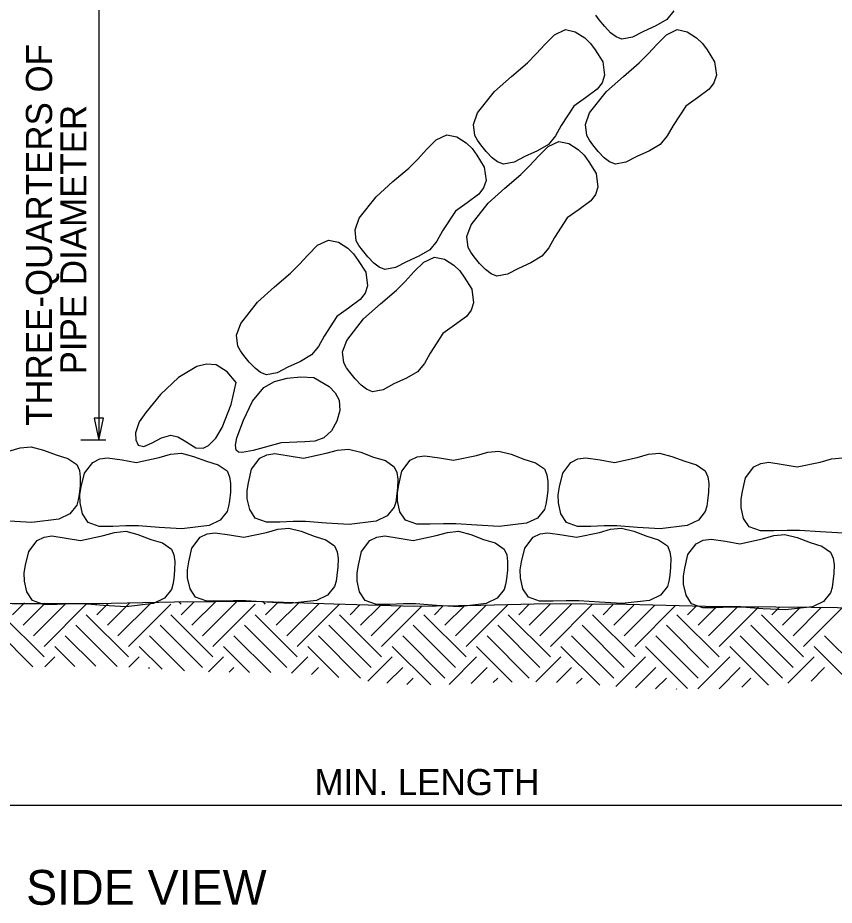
# Model space of a CAD drawing. Extents: x -439.1 to -407.9, y -458.1 to -436.2.
# Drawn here: x -428.69 to -424, y -444.35 to -439.25 of the extents above; entities that cross this region are included whole.
import ezdxf

# ---------------------------------------------------------------- set-up
doc = ezdxf.new("R2010")
doc.units = 0
doc.layers.add('Level 4', color=7, linetype='Continuous')

msp = doc.modelspace()

# ---------------------------------------------------------------- linework, layer by layer
at = {"layer": 'Level 4'}
for p, q in [((-428.2285, -439.0536), (-428.2285, -441.6773)), ((-428.1891, -441.6773), (-428.3314, -441.6773)), ((-427.6944, -442.741), (-427.5572, -442.6037)), ((-427.6338, -442.8016), (-427.4355, -442.6033)), ((-427.2701, -442.6197), (-427.2849, -442.6049)), ((-428.7249, -442.6804), (-428.6565, -442.612)), ((-428.6643, -442.741), (-428.5371, -442.6138)), ((-428.6037, -442.8016), (-428.4176, -442.6156)), ((-428.543, -442.8622), (-428.3006, -442.6197)), ((-428.24, -442.6197), (-428.2417, -442.618)), ((-428.24, -442.6804), (-428.1764, -442.6168)), ((-428.1794, -442.741), (-428.0525, -442.6141)), ((-428.1187, -442.8016), (-427.9282, -442.6111)), ((-428.0581, -442.8622), (-427.8157, -442.6197)), ((-427.7551, -442.6197), (-427.7676, -442.6072)), ((-427.7551, -442.6804), (-427.6801, -442.6054)), ((-427.5732, -442.8622), (-427.3308, -442.6197)), ((-427.2701, -442.6804), (-427.1967, -442.6069)), ((-427.2095, -442.741), (-427.0795, -442.611)), ((-427.1489, -442.8016), (-426.9629, -442.6155)), ((-427.0883, -442.8622), (-426.8464, -442.6203)), ((-426.7852, -442.6804), (-426.7299, -442.625)), ((-426.7246, -442.741), (-426.6124, -442.6288)), ((-426.664, -442.8016), (-426.4938, -442.6313)), ((-426.6034, -442.8622), (-426.3736, -442.6324)), ((-426.3003, -442.6804), (-426.2515, -442.6316)), ((-426.2397, -442.741), (-426.1279, -442.6292)), ((-426.1791, -442.8016), (-426.0036, -442.6261)), ((-426.1185, -442.8622), (-425.879, -442.6227)), ((-425.8154, -442.6804), (-425.7549, -442.6198)), ((-425.7548, -442.741), (-425.6323, -442.6184)), ((-425.6942, -442.8016), (-425.5129, -442.6203)), ((-425.6336, -442.8622), (-425.3936, -442.6222)), ((-425.3305, -442.6804), (-425.2743, -442.6241)), ((-425.2699, -442.741), (-425.1549, -442.626)), ((-425.2093, -442.8016), (-425.0356, -442.6279)), ((-425.1487, -442.8622), (-424.9163, -442.6298)), ((-424.8456, -442.6804), (-424.7969, -442.6317)), ((-424.785, -442.741), (-424.6776, -442.6336)), ((-424.7244, -442.8016), (-424.5582, -442.6354)), ((-424.6637, -442.8622), (-424.4383, -442.6367)), ((-424.3607, -442.6804), (-424.3181, -442.6378)), ((-424.3001, -442.741), (-424.1978, -442.6387)), ((-424.2394, -442.8016), (-424.0775, -442.6396)), ((-424.1788, -442.8622), (-423.9573, -442.6407)), ((-428.543, -442.9228), (-428.7855, -442.6804)), ((-428.0581, -442.9228), (-428.3006, -442.6804)), ((-427.5732, -442.9228), (-427.8157, -442.6804)), ((-427.0883, -442.9228), (-427.3308, -442.6804)), ((-426.6034, -442.9228), (-426.8458, -442.6804)), ((-426.1185, -442.9228), (-426.3609, -442.6804)), ((-425.6336, -442.9228), (-425.876, -442.6804)), ((-425.1487, -442.9228), (-425.3911, -442.6804)), ((-424.6637, -442.9228), (-424.9062, -442.6804)), ((-424.1788, -442.9228), (-424.4213, -442.6804)), ((-428.6075, -442.9796), (-428.8461, -442.741)), ((-428.1234, -442.9787), (-428.3612, -442.741)), ((-427.6338, -442.9834), (-427.8763, -442.741)), ((-427.1489, -442.9834), (-427.3914, -442.741)), ((-426.664, -442.9834), (-426.9065, -442.741)), ((-426.1791, -442.9834), (-426.4215, -442.741)), ((-425.6942, -442.9834), (-425.9366, -442.741)), ((-425.2093, -442.9834), (-425.4517, -442.741)), ((-424.7244, -442.9834), (-424.9668, -442.741)), ((-424.2394, -442.9834), (-424.4819, -442.741)), ((-428.2468, -442.9766), (-428.4218, -442.8016)), ((-427.7356, -443.0029), (-427.9369, -442.8016)), ((-427.2407, -443.0128), (-427.452, -442.8016)), ((-426.7246, -443.044), (-426.9671, -442.8016)), ((-426.2397, -443.044), (-426.4822, -442.8016)), ((-425.7548, -443.044), (-425.9972, -442.8016)), ((-425.2699, -443.044), (-425.5123, -442.8016)), ((-424.785, -443.044), (-425.0274, -442.8016)), ((-424.3001, -443.044), (-424.5425, -442.8016)), ((-423.8278, -443.0314), (-424.0576, -442.8016)), ((-428.3675, -442.9772), (-428.4824, -442.8622)), ((-427.8656, -442.9941), (-427.9975, -442.8622)), ((-427.3632, -443.0117), (-427.5126, -442.8622)), ((-426.8488, -443.0411), (-427.0277, -442.8622)), ((-426.3216, -443.0834), (-426.5428, -442.8622)), ((-425.853, -443.0671), (-426.0579, -442.8622)), ((-425.3493, -443.0858), (-425.5729, -442.8622)), ((-424.8456, -443.1047), (-425.088, -442.8622)), ((-424.381, -443.0843), (-424.6031, -442.8622)), ((-423.9382, -443.0422), (-424.1182, -442.8622)), ((-428.5388, -442.9792), (-428.4824, -442.9228)), ((-428.0565, -442.9818), (-427.9975, -442.9228)), ((-427.5985, -443.0087), (-427.5126, -442.9228)), ((-427.1213, -443.0164), (-427.0277, -442.9228)), ((-426.6822, -443.0622), (-426.5428, -442.9228)), ((-426.2163, -443.0813), (-426.0579, -442.9228)), ((-425.7166, -443.0665), (-425.5729, -442.9228)), ((-425.2578, -443.0926), (-425.088, -442.9228)), ((-424.787, -443.1067), (-424.6031, -442.9228)), ((-424.27, -443.0746), (-424.1182, -442.9228)), ((-427.9421, -442.9887), (-427.9369, -442.9834)), ((-427.4795, -443.0109), (-427.452, -442.9834)), ((-427.0072, -443.0236), (-426.9671, -442.9834)), ((-426.5727, -443.0739), (-426.4822, -442.9834)), ((-426.0897, -443.0759), (-425.9972, -442.9834)), ((-425.5989, -443.07), (-425.5123, -442.9834)), ((-425.1443, -443.1003), (-425.0274, -442.9834)), ((-424.6644, -443.1053), (-424.5425, -442.9834)), ((-424.1356, -443.0615), (-424.0576, -442.9834)), ((-426.4586, -443.0811), (-426.4215, -443.044)), ((-425.9629, -443.0704), (-425.9366, -443.044)), ((-425.484, -443.0763), (-425.4517, -443.044)), ((-425.029, -443.1062), (-424.9668, -443.044)), ((-424.5341, -443.0963), (-424.4819, -443.044)), ((-424.9095, -443.108), (-424.9062, -443.1047)), ((-431.8697, -443.7744), (-420.5223, -443.7744))]:
    msp.add_line(p, q, dxfattribs=at)
for points in [[(-424.9239, -439.2088), (-424.9645, -439.2577), (-425.0271, -439.2949), (-425.0992, -439.3274), (-425.1615, -439.3601), (-425.2224, -439.3716), (-425.2563, -439.358), (-425.2874, -439.3344), (-425.3218, -439.2986), (-425.3525, -439.26), (-425.3719, -439.2339)], [(-428.7461, -441.7401), (-428.6811, -441.7212), (-428.6178, -441.7154), (-428.5472, -441.7334), (-428.4732, -441.7614), (-428.4061, -441.7823), (-428.3549, -441.8172), (-428.3405, -441.8509), (-428.3352, -441.8895), (-428.3362, -441.9391), (-428.3418, -441.9881), (-428.3465, -442.0203), (-428.3549, -442.0505), (-428.3948, -442.1004), (-428.4583, -442.1305), (-428.6145, -442.1491), (-428.7445, -442.1419)], [(-423.9521, -442.2116), (-424.082, -442.2044), (-424.2018, -442.1952), (-424.2735, -442.1953), (-424.3497, -442.1984), (-424.4268, -442.1984), (-424.4909, -442.1754), (-424.5232, -442.1265), (-424.5369, -442.0637), (-424.5377, -442.0168), (-424.5304, -441.9717), (-424.5304, -441.9717), (-424.512, -441.8931), (-424.4647, -441.8304), (-424.4243, -441.8109), (-424.3792, -441.8041), (-424.2964, -441.8165), (-424.2149, -441.8304), (-424.0836, -441.8025), (-424.0186, -441.7837), (-423.9553, -441.7779)], [(-423.5303, -442.647), (-424.1356, -442.6392), (-424.7422, -442.6326), (-425.1968, -442.622), (-425.6511, -442.6181), (-426.0334, -442.6269), (-426.4158, -442.6326), (-426.8775, -442.6191), (-427.3391, -442.6037), (-427.7935, -442.6077), (-428.2481, -442.6181), (-428.7243, -442.6177), (-429.2003, -442.6037), (-429.6837, -442.5801), (-430.1669, -442.5604), (-430.5634, -442.556), (-430.9604, -442.5604), (-431.3146, -442.5644), (-431.6674, -442.546), (-431.7686, -442.5331), (-431.8694, -442.5172)]]:
    msp.add_lwpolyline(points, dxfattribs=at)
for points in [[(-425.3758, -439.4327), (-425.3332, -439.5013), (-425.3224, -439.5791), (-425.3371, -439.6215), (-425.3642, -439.6581), (-425.4315, -439.7079), (-425.499, -439.7557), (-425.5721, -439.8683), (-425.6047, -439.9275), (-425.6454, -439.9764), (-425.708, -440.0136), (-425.7801, -440.0461), (-425.8423, -440.0788), (-425.9033, -440.0903), (-425.9372, -440.0767), (-425.9683, -440.0531), (-426.0027, -440.0173), (-426.0334, -439.9788), (-426.0528, -439.9526), (-426.0682, -439.9253), (-426.0753, -439.8618), (-426.0517, -439.7957), (-425.9544, -439.6721), (-425.8574, -439.5853), (-425.7662, -439.5071), (-425.7155, -439.4563), (-425.6639, -439.4002), (-425.6094, -439.3457), (-425.5478, -439.3166), (-425.4904, -439.3284), (-425.4362, -439.363), (-425.4025, -439.3956), (-425.3758, -439.4327)], [(-424.7328, -439.4327), (-424.6902, -439.5013), (-424.6793, -439.5791), (-424.6941, -439.6215), (-424.7212, -439.6581), (-424.7884, -439.7079), (-424.8559, -439.7557), (-424.929, -439.8683), (-424.9617, -439.9275), (-425.0023, -439.9764), (-425.065, -440.0136), (-425.1371, -440.0461), (-425.1993, -440.0788), (-425.2602, -440.0903), (-425.2941, -440.0767), (-425.3253, -440.0531), (-425.3596, -440.0173), (-425.3903, -439.9788), (-425.4097, -439.9526), (-425.4252, -439.9253), (-425.4322, -439.8618), (-425.4086, -439.7957), (-425.3113, -439.6721), (-425.2143, -439.5853), (-425.1231, -439.5071), (-425.0725, -439.4563), (-425.0209, -439.4002), (-424.9664, -439.3457), (-424.9047, -439.3166), (-424.8473, -439.3284), (-424.7932, -439.363), (-424.7594, -439.3956), (-424.7328, -439.4327)], [(-426.0567, -440.038), (-426.0141, -440.1066), (-426.0033, -440.1844), (-426.018, -440.2267), (-426.0451, -440.2634), (-426.1124, -440.3132), (-426.1799, -440.3609), (-426.253, -440.4735), (-426.2856, -440.5328), (-426.3263, -440.5817), (-426.3889, -440.6188), (-426.461, -440.6514), (-426.5232, -440.6841), (-426.5842, -440.6955), (-426.6181, -440.6819), (-426.6492, -440.6583), (-426.6836, -440.6226), (-426.7143, -440.584), (-426.7337, -440.5579), (-426.7491, -440.5306), (-426.7562, -440.467), (-426.7326, -440.4009), (-426.6353, -440.2773), (-426.5383, -440.1905), (-426.4471, -440.1123), (-426.3964, -440.0616), (-426.3448, -440.0055), (-426.2903, -439.9509), (-426.2287, -439.9218), (-426.1713, -439.9337), (-426.1171, -439.9683), (-426.0834, -440.0009), (-426.0567, -440.038)], [(-425.4137, -440.0758), (-425.3711, -440.1444), (-425.3602, -440.2222), (-425.375, -440.2646), (-425.402, -440.3012), (-425.4693, -440.351), (-425.5368, -440.3988), (-425.6099, -440.5113), (-425.6426, -440.5706), (-425.6832, -440.6195), (-425.7458, -440.6567), (-425.8179, -440.6892), (-425.8802, -440.7219), (-425.9411, -440.7333), (-425.975, -440.7198), (-426.0061, -440.6962), (-426.0405, -440.6604), (-426.0712, -440.6218), (-426.0906, -440.5957), (-426.1061, -440.5684), (-426.1131, -440.5049), (-426.0895, -440.4387), (-425.9922, -440.3151), (-425.8952, -440.2283), (-425.804, -440.1502), (-425.7534, -440.0994), (-425.7018, -440.0433), (-425.6473, -439.9888), (-425.5856, -439.9596), (-425.5282, -439.9715), (-425.4741, -440.0061), (-425.4403, -440.0387), (-425.4137, -440.0758)], [(-426.7376, -440.6432), (-426.695, -440.7118), (-426.6842, -440.7896), (-426.6989, -440.832), (-426.726, -440.8686), (-426.7933, -440.9184), (-426.8608, -440.9662), (-426.9339, -441.0788), (-426.9665, -441.138), (-427.0071, -441.1869), (-427.0698, -441.2241), (-427.1419, -441.2566), (-427.2041, -441.2893), (-427.2651, -441.3008), (-427.299, -441.2872), (-427.3301, -441.2636), (-427.3645, -441.2278), (-427.3952, -441.1892), (-427.4146, -441.1631), (-427.43, -441.1358), (-427.4371, -441.0723), (-427.4134, -441.0061), (-427.3162, -440.8825), (-427.2192, -440.7958), (-427.128, -440.7176), (-427.0773, -440.6668), (-427.0257, -440.6107), (-426.9712, -440.5562), (-426.9096, -440.5271), (-426.8522, -440.5389), (-426.798, -440.5735), (-426.7643, -440.6061), (-426.7376, -440.6432)], [(-426.1283, -440.7403), (-426.0857, -440.8089), (-426.0749, -440.8867), (-426.0896, -440.9291), (-426.1167, -440.9657), (-426.184, -441.0155), (-426.2514, -441.0633), (-426.3246, -441.1759), (-426.3572, -441.2351), (-426.3978, -441.284), (-426.4605, -441.3212), (-426.5326, -441.3537), (-426.5948, -441.3864), (-426.6557, -441.3979), (-426.6897, -441.3843), (-426.7208, -441.3607), (-426.7552, -441.3249), (-426.7858, -441.2864), (-426.8053, -441.2602), (-426.8207, -441.2329), (-426.8277, -441.1694), (-426.8041, -441.1033), (-426.7068, -440.9797), (-426.6098, -440.8929), (-426.5186, -440.8147), (-426.468, -440.7639), (-426.4164, -440.7078), (-426.3619, -440.6533), (-426.3002, -440.6242), (-426.2428, -440.636), (-426.1887, -440.6706), (-426.155, -440.7032), (-426.1283, -440.7403)], [(-427.4399, -441.3455), (-427.4904, -441.2842), (-427.5553, -441.2445), (-427.6093, -441.2397), (-427.6653, -441.2538), (-427.7717, -441.3166), (-427.8738, -441.4133), (-427.9593, -441.5186), (-427.9963, -441.5711), (-428.017, -441.634), (-428.0153, -441.6752), (-428.0025, -441.7062), (-427.9692, -441.7127), (-427.9224, -441.6917), (-427.8688, -441.6635), (-427.815, -441.6484), (-427.7745, -441.6567), (-427.7375, -441.6778), (-427.6707, -441.7206), (-427.6284, -441.7228), (-427.5983, -441.7082), (-427.5566, -441.6653), (-427.5195, -441.6038), (-427.4683, -441.4715), (-427.4399, -441.3455)], [(-426.9926, -441.3166), (-426.9052, -441.3682), (-426.8703, -441.4038), (-426.8484, -441.4465), (-426.8439, -441.506), (-426.8604, -441.5676), (-426.8924, -441.6228), (-426.9349, -441.6629), (-426.9865, -441.6828), (-427.0444, -441.6871), (-427.1802, -441.6917), (-427.341, -441.7353), (-427.4042, -441.7482), (-427.4262, -441.7458), (-427.4399, -441.735), (-427.4439, -441.7054), (-427.4347, -441.6628), (-427.3966, -441.5619), (-427.3463, -441.4529), (-427.2812, -441.3743), (-427.2193, -441.3399), (-427.1463, -441.3194), (-427.0685, -441.3119), (-426.9926, -441.3166)], [(-428.2548, -441.5508), (-428.2285, -441.6773), (-428.2023, -441.5508)], [(-427.3689, -441.9214), (-427.3505, -441.8428), (-427.3032, -441.7801), (-427.2628, -441.7606), (-427.2177, -441.7538), (-427.1349, -441.7662), (-427.0534, -441.7801), (-426.9221, -441.7522), (-426.8571, -441.7334), (-426.7939, -441.7275), (-426.7233, -441.7456), (-426.6493, -441.7736), (-426.5821, -441.7944), (-426.531, -441.8294), (-426.5166, -441.863), (-426.5113, -441.9017), (-426.5123, -441.9513), (-426.5178, -442.0003), (-426.5226, -442.0325), (-426.531, -442.0627), (-426.5709, -442.1126), (-426.6344, -442.1427), (-426.7906, -442.1613), (-426.9205, -442.154), (-427.0403, -442.1448), (-427.112, -442.1449), (-427.1882, -442.1481), (-427.2653, -442.1481), (-427.3294, -442.1251), (-427.3617, -442.0762), (-427.3754, -442.0134), (-427.3762, -441.9665), (-427.3689, -441.9214)], [(-428.3295, -441.9457), (-428.3111, -441.8671), (-428.2638, -441.8044), (-428.2234, -441.7849), (-428.1783, -441.7782), (-428.0955, -441.7905), (-428.014, -441.8044), (-427.8827, -441.7765), (-427.8177, -441.7577), (-427.7545, -441.7519), (-427.6839, -441.7699), (-427.6099, -441.7979), (-427.5427, -441.8187), (-427.4916, -441.8537), (-427.4772, -441.8873), (-427.4719, -441.926), (-427.4729, -441.9756), (-427.4784, -442.0246), (-427.4832, -442.0568), (-427.4916, -442.087), (-427.5315, -442.1369), (-427.595, -442.167), (-427.7512, -442.1856), (-427.8811, -442.1784), (-428.0009, -442.1692), (-428.0726, -442.1693), (-428.1488, -442.1725), (-428.2259, -442.1725), (-428.29, -442.1494), (-428.3223, -442.1005), (-428.3361, -442.0377), (-428.3369, -441.9908), (-428.3295, -441.9457)], [(-426.5056, -441.9336), (-426.4872, -441.8549), (-426.4398, -441.7923), (-426.3994, -441.7727), (-426.3544, -441.766), (-426.2716, -441.7783), (-426.1901, -441.7923), (-426.0588, -441.7644), (-425.9938, -441.7455), (-425.9305, -441.7397), (-425.8599, -441.7577), (-425.786, -441.7857), (-425.7188, -441.8066), (-425.6677, -441.8416), (-425.6533, -441.8752), (-425.6479, -441.9138), (-425.6489, -441.9635), (-425.6545, -442.0124), (-425.6593, -442.0446), (-425.6677, -442.0749), (-425.7076, -442.1248), (-425.7711, -442.1548), (-425.9272, -442.1734), (-426.0572, -442.1662), (-426.177, -442.157), (-426.2487, -442.1571), (-426.3248, -442.1603), (-426.4019, -442.1603), (-426.4661, -442.1373), (-426.4983, -442.0883), (-426.5121, -442.0256), (-426.5129, -441.9787), (-426.5056, -441.9336)], [(-425.5814, -441.9457), (-425.5631, -441.8671), (-425.5157, -441.8044), (-425.4753, -441.7849), (-425.4303, -441.7782), (-425.3475, -441.7905), (-425.266, -441.8044), (-425.1347, -441.7765), (-425.0697, -441.7577), (-425.0064, -441.7519), (-424.9358, -441.7699), (-424.8618, -441.7979), (-424.7947, -441.8187), (-424.7435, -441.8537), (-424.7291, -441.8873), (-424.7238, -441.926), (-424.7248, -441.9756), (-424.7304, -442.0246), (-424.7352, -442.0568), (-424.7435, -442.087), (-424.7835, -442.1369), (-424.8469, -442.167), (-425.0031, -442.1856), (-425.1331, -442.1784), (-425.2528, -442.1692), (-425.3246, -442.1693), (-425.4007, -442.1725), (-425.4778, -442.1725), (-425.542, -442.1494), (-425.5742, -442.1005), (-425.588, -442.0377), (-425.5888, -441.9908), (-425.5814, -441.9457)], [(-427.7116, -442.3763), (-427.6933, -442.2977), (-427.6459, -442.235), (-427.6055, -442.2154), (-427.5605, -442.2087), (-427.4777, -442.221), (-427.3962, -442.235), (-427.2649, -442.2071), (-427.1999, -442.1883), (-427.1366, -442.1824), (-427.066, -442.2004), (-426.992, -442.2284), (-426.9249, -442.2493), (-426.8737, -442.2843), (-426.8594, -442.3179), (-426.854, -442.3566), (-426.855, -442.4062), (-426.8606, -442.4551), (-426.8654, -442.4874), (-426.8737, -442.5176), (-426.9137, -442.5675), (-426.9771, -442.5975), (-427.1333, -442.6161), (-427.2633, -442.6089), (-427.3831, -442.5997), (-427.4548, -442.5998), (-427.5309, -442.603), (-427.608, -442.603), (-427.6722, -442.58), (-427.7044, -442.531), (-427.7182, -442.4683), (-427.719, -442.4214), (-427.7116, -442.3763)], [(-425.7992, -442.3763), (-425.7808, -442.2977), (-425.7335, -442.235), (-425.6931, -442.2154), (-425.6481, -442.2087), (-425.5652, -442.221), (-425.4838, -442.235), (-425.3524, -442.2071), (-425.2875, -442.1883), (-425.2242, -442.1824), (-425.1536, -442.2004), (-425.0796, -442.2284), (-425.0125, -442.2493), (-424.9613, -442.2843), (-424.9469, -442.3179), (-424.9416, -442.3566), (-424.9426, -442.4062), (-424.9482, -442.4551), (-424.9529, -442.4874), (-424.9613, -442.5176), (-425.0012, -442.5675), (-425.0647, -442.5975), (-425.2209, -442.6161), (-425.3509, -442.6089), (-425.4706, -442.5997), (-425.5423, -442.5998), (-425.6185, -442.603), (-425.6956, -442.603), (-425.7598, -442.58), (-425.792, -442.531), (-425.8058, -442.4683), (-425.8066, -442.4214), (-425.7992, -442.3763)], [(-428.6495, -442.3947), (-428.6311, -442.316), (-428.5838, -442.2534), (-428.5434, -442.2338), (-428.4983, -442.2271), (-428.4155, -442.2394), (-428.334, -442.2534), (-428.2027, -442.2255), (-428.1377, -442.2066), (-428.0744, -442.2008), (-428.0039, -442.2188), (-427.9299, -442.2468), (-427.8627, -442.2677), (-427.8116, -442.3027), (-427.7972, -442.3363), (-427.7919, -442.3749), (-427.7929, -442.4246), (-427.7984, -442.4735), (-427.8032, -442.5057), (-427.8116, -442.536), (-427.8515, -442.5858), (-427.915, -442.6159), (-428.0712, -442.6345), (-428.2011, -442.6273), (-428.3209, -442.6181), (-428.3926, -442.6182), (-428.4688, -442.6214), (-428.5459, -442.6214), (-428.61, -442.5984), (-428.6423, -442.5494), (-428.656, -442.4867), (-428.6568, -442.4398), (-428.6495, -442.3947)], [(-426.737, -442.3947), (-426.7187, -442.316), (-426.6713, -442.2534), (-426.6309, -442.2338), (-426.5859, -442.2271), (-426.5031, -442.2394), (-426.4216, -442.2534), (-426.2903, -442.2255), (-426.2253, -442.2066), (-426.162, -442.2008), (-426.0914, -442.2188), (-426.0174, -442.2468), (-425.9503, -442.2677), (-425.8991, -442.3027), (-425.8847, -442.3363), (-425.8794, -442.3749), (-425.8804, -442.4246), (-425.886, -442.4735), (-425.8908, -442.5057), (-425.8991, -442.536), (-425.9391, -442.5858), (-426.0025, -442.6159), (-426.1587, -442.6345), (-426.2887, -442.6273), (-426.4084, -442.6181), (-426.4801, -442.6182), (-426.5563, -442.6214), (-426.6334, -442.6214), (-426.6976, -442.5984), (-426.7298, -442.5494), (-426.7436, -442.4867), (-426.7444, -442.4398), (-426.737, -442.3947)], [(-424.8614, -442.4131), (-424.843, -442.3344), (-424.7957, -442.2718), (-424.7553, -442.2522), (-424.7102, -442.2455), (-424.6274, -442.2578), (-424.5459, -442.2718), (-424.4146, -442.2439), (-424.3496, -442.225), (-424.2863, -442.2192), (-424.2158, -442.2372), (-424.1418, -442.2652), (-424.0746, -442.2861), (-424.0235, -442.321), (-424.0091, -442.3547), (-424.0038, -442.3933), (-424.0048, -442.4429), (-424.0103, -442.4919), (-424.0151, -442.5241), (-424.0235, -442.5543), (-424.0634, -442.6042), (-424.1269, -442.6343), (-424.2831, -442.6529), (-424.413, -442.6457), (-424.5328, -442.6365), (-424.6045, -442.6366), (-424.6807, -442.6398), (-424.7578, -442.6398), (-424.8219, -442.6168), (-424.8542, -442.5678), (-424.8679, -442.5051), (-424.8687, -442.4581), (-424.8614, -442.4131)]]:
    msp.add_lwpolyline(points, close=True, dxfattribs=at)

# ---------------------------------------------------------------- texts
for s, p in [('THREE-QUARTERS OF', (-428.4975, -441.5949)), ('PIPE DIAMETER', (-428.2999, -441.2984))]:
    msp.add_text(s, height=0.15, rotation=90, dxfattribs=at).set_placement(p)
for s, height, p in [('MIN. LENGTH', 0.15, (-426.9897, -443.7173)), ('SIDE VIEW', 0.2, (-428.6464, -444.3475))]:
    msp.add_text(s, height=height, dxfattribs=at).set_placement(p)

doc.saveas('drawing.dxf')
